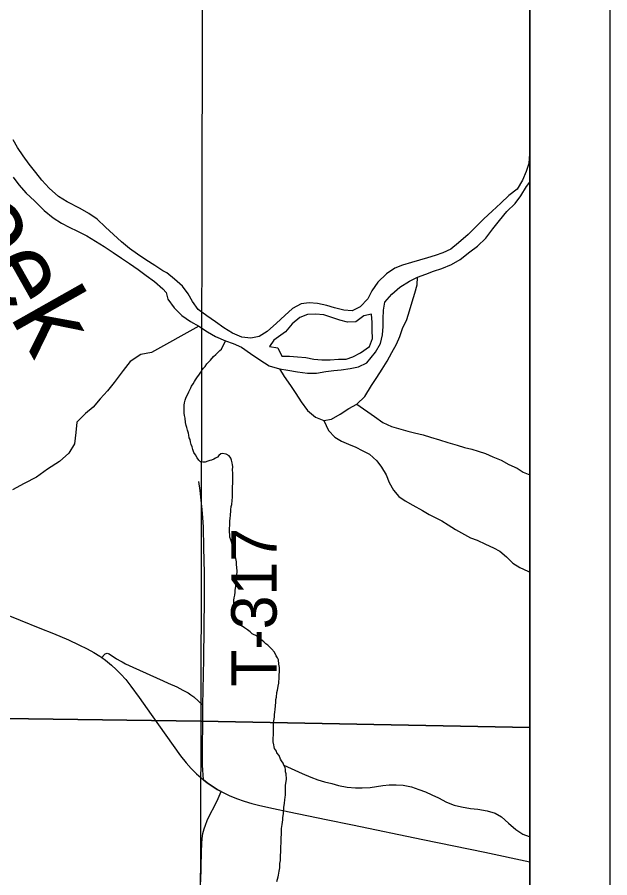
# Model space of a CAD drawing. Extents: x 0 to 34, y 0 to 22.
# Drawn here: x 8.26 to 9, y 17.023 to 18.098 of the extents above; entities that cross this region are included whole.
import ezdxf

# ---------------------------------------------------------------- set-up
doc = ezdxf.new("R2010")
doc.units = 0
for name, color, linetype in [('GM_X_Corporation', 7, 'Continuous'), ('GM_X_Major_River', 7, 'Continuous'), ('GM_X_Major_River_Text', 7, 'Continuous'), ('GM_X_Minor_River', 7, 'Continuous'), ('GM_X_State_Route', 7, 'Continuous'), ('GM_X_Township_Road', 7, 'Continuous'), ('GM_X_Township_Road_Text', 7, 'Continuous'), ('SH_Data', 7, 'Continuous')]:
    doc.layers.add(name, color=color, linetype=linetype)

msp = doc.modelspace()

# ---------------------------------------------------------------- linework, layer by layer
at = {"layer": 'GM_X_Corporation'}
msp.add_lwpolyline([(3.4463, 14.1), (8.9, 14.1), (8.9, 18.3034), (8.7111, 18.3046), (8.4971, 18.3046), (7.581, 18.3149)], dxfattribs=at)
for points in [[(8.4911, 18.3026), (8.489, 17.2189), (7.4742, 17.2327), (7.4788, 18.3152)], [(8.9, 17.211), (8.9, 18.3013), (8.4911, 18.3026), (8.489, 17.2189)], [(8.489, 17.2189), (8.4859, 16.2068), (7.4675, 16.2282), (7.4742, 17.2327)], [(8.9, 16.203), (8.9, 17.211), (8.489, 17.2189), (8.4859, 16.2068)]]:
    msp.add_lwpolyline(points, close=True, dxfattribs=at)
at = {"layer": 'GM_X_Major_River'}
for points in [[(8.4468, 17.7788), (8.4417, 17.7815), (8.4316, 17.7881), (8.4204, 17.7951), (8.4099, 17.8025), (8.4001, 17.8095), (8.39, 17.8177), (8.3699, 17.8362), (8.3595, 17.8459), (8.3493, 17.8529), (8.3384, 17.8592), (8.3223, 17.8678), (8.3114, 17.8745), (8.2998, 17.8849), (8.2905, 17.8946), (8.2831, 17.9042), (8.2746, 17.9146), (8.2672, 17.9253), (8.2602, 17.9357), (8.2547, 17.9453)], [(8.9, 17.9302), (8.8998, 17.9278), (8.899, 17.9157), (8.8957, 17.9055), (8.8908, 17.8946), (8.8844, 17.8834), (8.8739, 17.8758), (8.8641, 17.8662), (8.8532, 17.8559), (8.8426, 17.8464), (8.8329, 17.8368), (8.8231, 17.8268), (8.811, 17.8166), (8.8013, 17.8085), (8.7916, 17.8039), (8.7817, 17.8007), (8.7721, 17.7976), (8.7625, 17.7949), (8.7521, 17.7918), (8.741, 17.7887), (8.7314, 17.7848), (8.7209, 17.7779), (8.7104, 17.7672), (8.7028, 17.7564), (8.6976, 17.7467), (8.6882, 17.7364), (8.6782, 17.7317), (8.6676, 17.7324), (8.6562, 17.7354), (8.6464, 17.738), (8.6347, 17.7407), (8.6245, 17.7417), (8.6146, 17.7401), (8.6038, 17.7344), (8.594, 17.7259), (8.5835, 17.716), (8.5722, 17.7057), (8.5621, 17.6996), (8.5518, 17.6972), (8.5404, 17.6987), (8.5288, 17.7036), (8.518, 17.7104), (8.5075, 17.7179), (8.4967, 17.7251), (8.486, 17.7334), (8.4786, 17.7431), (8.4732, 17.7528), (8.4663, 17.7625), (8.4563, 17.7711), (8.4468, 17.7788)], [(8.2546, 17.8987), (8.2616, 17.889), (8.2709, 17.8786), (8.2813, 17.869), (8.2936, 17.857), (8.3045, 17.8477), (8.315, 17.841), (8.3247, 17.8359), (8.3349, 17.8312), (8.3466, 17.8253), (8.3574, 17.8186), (8.3683, 17.812), (8.3796, 17.8046), (8.3901, 17.7972), (8.4002, 17.7906), (8.411, 17.7832), (8.4208, 17.7758), (8.4312, 17.768), (8.4417, 17.7591), (8.446, 17.7543)], [(8.446, 17.7543), (8.448, 17.7463), (8.456, 17.7354), (8.4656, 17.7257), (8.4764, 17.7181), (8.4865, 17.7125), (8.4973, 17.7053), (8.5074, 17.6993), (8.5198, 17.694), (8.5295, 17.6907), (8.54, 17.6862), (8.5512, 17.6783), (8.5628, 17.6703), (8.5747, 17.6627), (8.5875, 17.6589), (8.5977, 17.6575), (8.6098, 17.6552), (8.6223, 17.6537), (8.6337, 17.6537), (8.6455, 17.6556), (8.6551, 17.6569), (8.6646, 17.6577), (8.6757, 17.6593), (8.686, 17.6616), (8.6964, 17.6666), (8.7074, 17.68), (8.7134, 17.6908), (8.716, 17.7017), (8.7171, 17.712), (8.717, 17.7214), (8.7173, 17.7325), (8.7191, 17.7423), (8.7278, 17.7523), (8.7379, 17.7611), (8.7496, 17.7687), (8.76, 17.7737), (8.7703, 17.7772), (8.7799, 17.7811), (8.7903, 17.7845), (8.8022, 17.7895), (8.813, 17.7956), (8.8251, 17.8051), (8.8348, 17.8124), (8.845, 17.8224), (8.8537, 17.8339), (8.8623, 17.8442), (8.8714, 17.8554), (8.882, 17.8657), (8.8887, 17.8753), (8.8959, 17.8869), (8.9, 17.8924)], [(8.6707, 17.6712), (8.6791, 17.674), (8.6888, 17.679), (8.6997, 17.687), (8.7037, 17.6968), (8.7033, 17.7074), (8.7032, 17.7169), (8.7024, 17.7272), (8.6928, 17.7252), (8.6827, 17.7179), (8.6724, 17.7175), (8.6626, 17.7197), (8.6528, 17.7234), (8.6427, 17.7264), (8.6324, 17.7274), (8.6226, 17.727), (8.6129, 17.7231), (8.6032, 17.7154), (8.5949, 17.7054), (8.5804, 17.695)], [(8.5804, 17.695), (8.575, 17.687)], [(8.575, 17.687), (8.5852, 17.6852), (8.5902, 17.6748), (8.5997, 17.6749), (8.61, 17.6742), (8.6202, 17.6731), (8.6304, 17.6713), (8.6403, 17.6702), (8.6509, 17.6703), (8.6612, 17.6711), (8.6707, 17.6712)]]:
    msp.add_lwpolyline(points, dxfattribs=at)
at = {"layer": 'GM_X_Minor_River'}
for points in [[(8.5875, 17.6589), (8.5933, 17.6493), (8.601, 17.6384), (8.6079, 17.6283), (8.6144, 17.6179), (8.6224, 17.607), (8.6325, 17.5987), (8.6426, 17.5946), (8.6525, 17.5962), (8.663, 17.6023), (8.6742, 17.6096), (8.6839, 17.615), (8.694, 17.6246), (8.7024, 17.6384), (8.7092, 17.6484), (8.7155, 17.6585), (8.7219, 17.6685), (8.7279, 17.6793), (8.7336, 17.6898), (8.7376, 17.6996), (8.741, 17.7093), (8.7466, 17.7206), (8.75, 17.7315), (8.753, 17.7428), (8.7563, 17.7537), (8.7593, 17.7642), (8.76, 17.7737)], [(8.4865, 17.7125), (8.4277, 17.6795), (8.4143, 17.6771), (8.4008, 17.6684), (8.3922, 17.6568), (8.3808, 17.6419), (8.3726, 17.6315), (8.3633, 17.6215), (8.3547, 17.6111), (8.345, 17.6034), (8.3341, 17.5926), (8.333, 17.5794), (8.3315, 17.5654), (8.3244, 17.5538), (8.3124, 17.5435), (8.2977, 17.5336), (8.2838, 17.5237), (8.2685, 17.5157), (8.2539, 17.5081)], [(8.5305, 17.4328), (8.5291, 17.4366), (8.5284, 17.4393), (8.5277, 17.4416), (8.5266, 17.4454), (8.5255, 17.4488), (8.5252, 17.4523), (8.5249, 17.4549), (8.5252, 17.4682), (8.5257, 17.4728), (8.5261, 17.4754), (8.5262, 17.4777), (8.5266, 17.4803), (8.5267, 17.483), (8.5271, 17.4872), (8.528, 17.4898), (8.5281, 17.4947), (8.5285, 17.4989), (8.5292, 17.5293), (8.5289, 17.5327), (8.529, 17.5369), (8.5287, 17.5392), (8.5283, 17.5418), (8.5273, 17.5449), (8.5266, 17.5476), (8.5244, 17.5506), (8.521, 17.5526), (8.5164, 17.5535), (8.5142, 17.5528), (8.5118, 17.5509), (8.5099, 17.5487), (8.5076, 17.5476), (8.5053, 17.5461), (8.5026, 17.5451), (8.5003, 17.5444), (8.498, 17.5436), (8.4946, 17.5426), (8.4915, 17.5423), (8.4889, 17.5431), (8.4866, 17.545), (8.4844, 17.5481), (8.4826, 17.5516), (8.4804, 17.5547), (8.479, 17.5585), (8.4783, 17.5616), (8.4772, 17.5646), (8.4761, 17.5681), (8.4758, 17.5707), (8.4747, 17.573), (8.474, 17.5761), (8.4737, 17.5788), (8.4726, 17.5826), (8.4716, 17.5856), (8.4709, 17.5883), (8.4702, 17.5921), (8.4695, 17.5975), (8.4689, 17.6009), (8.4685, 17.6036), (8.4682, 17.6066), (8.4684, 17.6138), (8.4688, 17.6168), (8.4697, 17.6199), (8.4705, 17.6225), (8.4717, 17.6255), (8.4733, 17.6281), (8.4741, 17.6304), (8.4753, 17.6327), (8.4765, 17.6353), (8.4776, 17.6375), (8.4796, 17.6405), (8.4812, 17.6432), (8.4824, 17.6454), (8.4843, 17.648), (8.4875, 17.6525), (8.489, 17.6551), (8.491, 17.6577), (8.4926, 17.66), (8.4945, 17.6622), (8.4965, 17.6652), (8.4988, 17.6674), (8.5012, 17.6701), (8.5051, 17.6745), (8.5078, 17.6771), (8.5105, 17.6793), (8.5128, 17.6819), (8.5151, 17.6838), (8.5198, 17.694)], [(8.6839, 17.615), (8.7059, 17.5997), (8.7167, 17.5919), (8.7272, 17.5871), (8.7476, 17.5813), (8.7559, 17.5792), (8.7669, 17.5767), (8.776, 17.5738), (8.7873, 17.5702), (8.7978, 17.5669), (8.8092, 17.5636), (8.8186, 17.5607), (8.8277, 17.5586), (8.8356, 17.5561), (8.8446, 17.5533), (8.8537, 17.5493), (8.8642, 17.5452), (8.874, 17.5397), (8.8841, 17.5349)], [(8.6426, 17.5946), (8.6485, 17.582), (8.6567, 17.5739), (8.6649, 17.5687), (8.6736, 17.5651), (8.6826, 17.5611), (8.6905, 17.5571), (8.6999, 17.5524), (8.7092, 17.5442), (8.7147, 17.5361), (8.7206, 17.5268), (8.7242, 17.5173), (8.7297, 17.5076), (8.7363, 17.4995), (8.7446, 17.494), (8.754, 17.4889), (8.766, 17.4821), (8.7742, 17.477), (8.79, 17.4691), (8.7982, 17.4643), (8.8072, 17.4584), (8.826, 17.4481), (8.8343, 17.4449), (8.8448, 17.4401), (8.8546, 17.4353), (8.8625, 17.4313), (8.8711, 17.4243), (8.8789, 17.4165), (8.8875, 17.411), (8.8976, 17.4062), (8.9, 17.405)], [(8.8841, 17.5349), (8.892, 17.5302), (8.9, 17.5265)], [(8.5901, 17.0828), (8.5901, 17.085), (8.5905, 17.0873), (8.5906, 17.09), (8.591, 17.093), (8.5915, 17.0956), (8.5915, 17.0983), (8.5924, 17.1036), (8.5925, 17.1066), (8.5929, 17.1093), (8.593, 17.1116), (8.5938, 17.1161), (8.5939, 17.121), (8.5944, 17.1237), (8.5948, 17.1271), (8.5951, 17.1392), (8.5956, 17.1438), (8.596, 17.1464), (8.5961, 17.1487), (8.5957, 17.151), (8.5958, 17.1533), (8.5951, 17.1556), (8.5948, 17.1586), (8.5944, 17.1609), (8.593, 17.164), (8.5919, 17.1667), (8.5901, 17.1694), (8.5886, 17.1717), (8.5868, 17.1759), (8.5842, 17.1794), (8.5835, 17.1817), (8.5813, 17.1847), (8.5806, 17.187), (8.5802, 17.1893), (8.5796, 17.1931), (8.5799, 17.2064), (8.5799, 17.2102), (8.5801, 17.2174), (8.5806, 17.2216), (8.581, 17.2246), (8.5811, 17.2269), (8.5815, 17.2307), (8.582, 17.2333), (8.5825, 17.2386), (8.5829, 17.2424), (8.583, 17.2462), (8.5835, 17.2489), (8.584, 17.2546), (8.5848, 17.2576), (8.5852, 17.2599), (8.5857, 17.2629), (8.5865, 17.2663), (8.5866, 17.2689), (8.587, 17.2716), (8.5873, 17.286), (8.5866, 17.2902), (8.586, 17.2955), (8.5849, 17.2982), (8.5834, 17.3005), (8.5813, 17.3051), (8.5776, 17.3094), (8.575, 17.3117), (8.5727, 17.3141), (8.5705, 17.3156), (8.5679, 17.318), (8.5656, 17.3199), (8.5615, 17.3227), (8.5589, 17.3254), (8.5559, 17.327), (8.5533, 17.3282), (8.5507, 17.3305), (8.5473, 17.3329), (8.5436, 17.3356), (8.5406, 17.3376), (8.5391, 17.3399), (8.5361, 17.3426), (8.5336, 17.3465), (8.5321, 17.3499), (8.531, 17.3534), (8.5307, 17.3557), (8.53, 17.3595), (8.5303, 17.3701), (8.5307, 17.3731), (8.5315, 17.3762), (8.532, 17.3803), (8.5321, 17.3826), (8.5325, 17.3849), (8.5329, 17.3875), (8.5334, 17.3909), (8.5334, 17.3932), (8.5339, 17.3955), (8.5343, 17.4), (8.5345, 17.4072), (8.5342, 17.4099), (8.5339, 17.4156), (8.5336, 17.4179), (8.5329, 17.4221), (8.5322, 17.4248), (8.5319, 17.427), (8.5308, 17.4301), (8.5305, 17.4328)], [(8.593, 17.164), (8.6159, 17.1536), (8.6265, 17.1492), (8.6351, 17.1459), (8.6438, 17.1431), (8.6529, 17.141), (8.6612, 17.1385), (8.6718, 17.1367), (8.6824, 17.1357), (8.6907, 17.1356), (8.7006, 17.1361), (8.7166, 17.1388), (8.7246, 17.1393), (8.733, 17.1395), (8.7417, 17.139), (8.7523, 17.1368), (8.7614, 17.1336), (8.7697, 17.1307), (8.7779, 17.1271), (8.7862, 17.1231), (8.796, 17.118), (8.8054, 17.114), (8.8148, 17.1119), (8.8262, 17.1101), (8.8353, 17.1091), (8.847, 17.107), (8.8568, 17.1041), (8.8647, 17.0993), (8.8733, 17.0915), (8.8826, 17.0837), (8.8912, 17.0779), (8.8991, 17.075), (8.9, 17.0749)], [(8.5841, 17.0187), (8.5857, 17.0244), (8.5862, 17.0266), (8.587, 17.0316), (8.5879, 17.0357), (8.588, 17.0414), (8.5885, 17.0448), (8.5886, 17.052), (8.5891, 17.0551), (8.5895, 17.074), (8.5899, 17.0771), (8.5901, 17.0828)]]:
    msp.add_lwpolyline(points, dxfattribs=at)
at = {"layer": 'GM_X_State_Route'}
for points in [[(8.164, 17.3855), (8.1659, 17.3848), (8.1992, 17.3714), (8.2387, 17.3551), (8.2882, 17.3352)], [(8.2882, 17.3352), (8.305, 17.3284), (8.3239, 17.3204), (8.3368, 17.3145), (8.3473, 17.3092), (8.3554, 17.3046), (8.3628, 17.3), (8.3653, 17.2983), (8.3699, 17.295), (8.3775, 17.2889), (8.3835, 17.2835), (8.3892, 17.2778), (8.3953, 17.2709), (8.4019, 17.2627), (8.4122, 17.2487), (8.4272, 17.2274), (8.4636, 17.1755), (8.4708, 17.1669), (8.4771, 17.16), (8.4837, 17.1534), (8.4923, 17.1459)], [(8.4923, 17.1459), (8.497, 17.142), (8.5031, 17.1377), (8.5095, 17.1337), (8.5145, 17.131)], [(8.5145, 17.131), (8.5161, 17.1301), (8.5246, 17.1262), (8.5339, 17.1224), (8.5433, 17.1191), (8.5528, 17.1162), (8.563, 17.1135), (8.5801, 17.1098), (8.5995, 17.1056), (8.6457, 17.0961), (8.6785, 17.0896), (8.7666, 17.0713), (8.8439, 17.0555), (8.9, 17.0432)]]:
    msp.add_lwpolyline(points, dxfattribs=at)
at = {"layer": 'GM_X_Township_Road'}
for points in [[(8.4929, 17.4354), (8.4923, 17.4614), (8.4916, 17.4732), (8.4909, 17.4835), (8.4897, 17.4949), (8.4883, 17.5072), (8.4865, 17.5182)], [(8.4917, 17.2391), (8.493, 17.2963), (8.4933, 17.336), (8.4936, 17.3714), (8.4937, 17.3882), (8.4937, 17.4044), (8.4929, 17.4354)], [(8.3653, 17.2983), (8.3687, 17.3023), (8.3698, 17.3032), (8.3708, 17.3036), (8.372, 17.3038), (8.3734, 17.3036), (8.3748, 17.3031), (8.384, 17.297), (8.3893, 17.2939), (8.3909, 17.293)], [(8.3909, 17.293), (8.395, 17.2907), (8.4042, 17.2863), (8.442, 17.2693), (8.4483, 17.2666), (8.459, 17.2617), (8.4667, 17.2578), (8.4732, 17.2543), (8.4767, 17.252), (8.4804, 17.2492), (8.4917, 17.2391)], [(8.4923, 17.1459), (8.4914, 17.1642), (8.4917, 17.2391)], [(8.5145, 17.131), (8.5095, 17.1337), (8.5031, 17.1377), (8.497, 17.142), (8.4923, 17.1459)], [(8.4891, 17.0181), (8.4898, 17.0559), (8.4903, 17.066), (8.4909, 17.0724), (8.4918, 17.0786), (8.4933, 17.0845), (8.4948, 17.0892), (8.497, 17.0949), (8.5013, 17.1037), (8.5056, 17.112), (8.5109, 17.1225), (8.5145, 17.131)]]:
    msp.add_lwpolyline(points, dxfattribs=at)
at = {"layer": 'SH_Data'}
for p, q in [((9, 21), (9, 14)), ((8.9, 20.9), (8.9, 14.1)), ((8.9, 20.9), (8.9, 14.1)), ((8.9, 20.9), (8.9, 14.1))]:
    msp.add_line(p, q, dxfattribs=at)

# ---------------------------------------------------------------- texts
at = {"layer": 'GM_X_Major_River_Text'}
msp.add_text('Creek', height=0.09467, rotation=299.4619, dxfattribs=at).set_placement((8.115, 17.9633))
at = {"layer": 'GM_X_Township_Road_Text'}
msp.add_text('T-317', height=0.05682, rotation=90, dxfattribs=at).set_placement((8.5839, 17.262))

doc.saveas('drawing.dxf')
